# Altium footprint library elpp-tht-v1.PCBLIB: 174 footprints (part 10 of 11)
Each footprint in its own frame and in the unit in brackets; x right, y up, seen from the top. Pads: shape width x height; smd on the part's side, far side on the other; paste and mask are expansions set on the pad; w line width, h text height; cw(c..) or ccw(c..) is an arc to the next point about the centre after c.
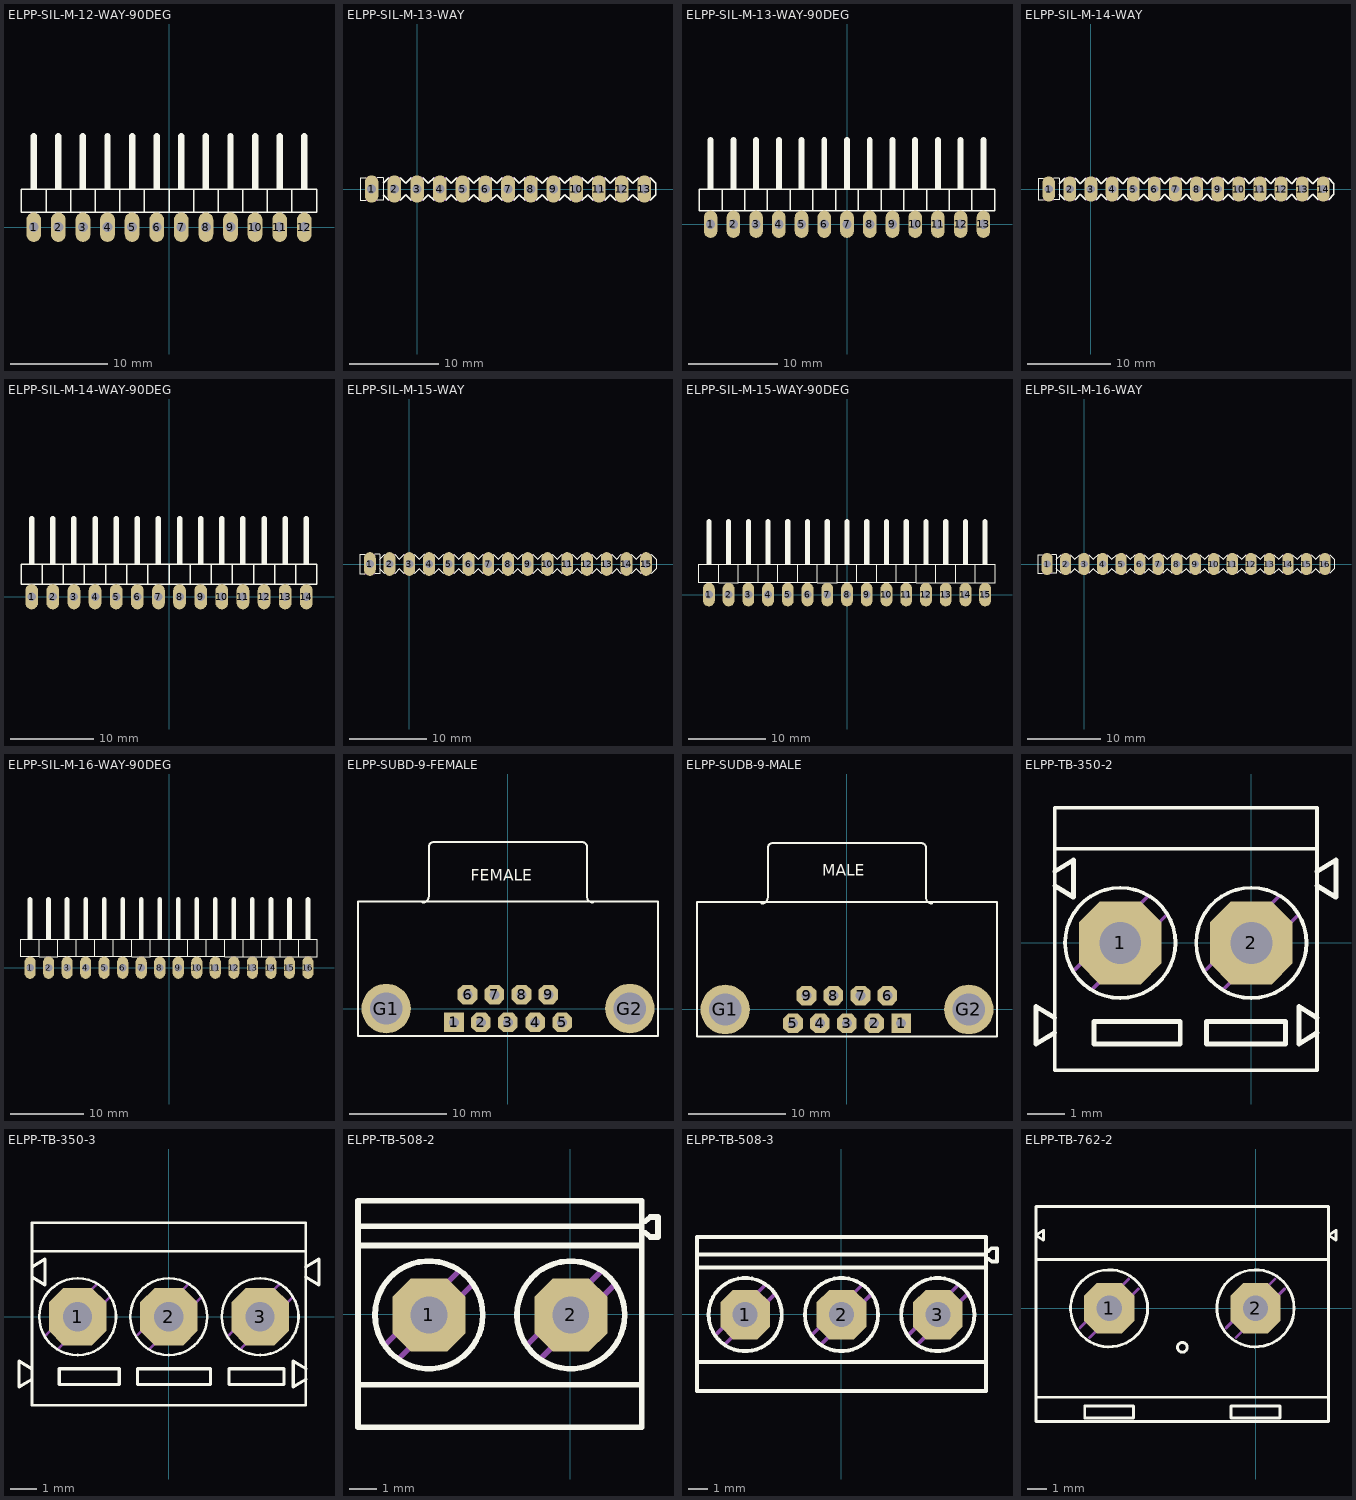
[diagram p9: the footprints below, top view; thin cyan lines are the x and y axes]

## ELPP-SIL-M-12-WAY-90DEG [mil]
pads (12):
  oval 60x120 hole 40: 1(-550,0) 2(-450,0) 3(-350,0) 4(-250,0) 5(-150,0) 6(-50,0) 7(50,0) 8(150,0) 9(250,0) 10(350,0) 11(450,0) 12(550,0)
Top Overlay:
  rectangle: 437,155 463,185
  rectangle: 537,155 563,185
  rectangle: -63,155 -37,185
  rectangle: 37,155 63,185
  rectangle: 137,155 163,185
  rectangle: 237,155 263,185
  rectangle: 337,155 363,185
  rectangle: -563,155 -537,185
  rectangle: -463,155 -437,185
  rectangle: -363,155 -337,185
  rectangle: -263,155 -237,185
  rectangle: -163,155 -137,185
  lines w6: -500,60 -500,155 ; -500,60 -600,60 -600,155 -500,155 ; -500,60 -400,60 ; -500,155 -400,155 ; -400,60 -300,60 ; -400,60 -400,155 ; -400,155 -300,155 ; -300,60 -200,60 ; -300,60 -300,155 ; -300,155 -200,155 ; -200,60 -100,60 ; -200,60 -200,155 ; -200,155 -100,155 ; -100,60 0,60 ; -100,60 -100,155 ; -100,155 0,155 ; 0,60 0,155 ; 0,60 100,60 ; 0,155 100,155 ; 100,60 200,60 ; 100,60 100,155 ; 100,155 200,155 ; 200,60 300,60 ; 200,60 200,155 ; 200,155 300,155 ; 300,60 400,60 ; 300,60 300,155 ; 300,155 400,155 ; 400,60 500,60 ; 400,60 400,155 ; 400,155 500,155 ; 500,60 500,155 ; 500,60 600,60 600,155 500,155
  lines w26: -550,185 -550,370 ; -450,185 -450,370 ; -350,185 -350,370 ; -250,185 -250,370 ; -150,185 -150,370 ; -50,185 -50,370 ; 50,185 50,370 ; 150,185 150,370 ; 250,185 250,370 ; 350,185 350,370 ; 450,185 450,370 ; 550,185 550,370
Mechanical 2:
  text ">NAME" at -610,140 h42.5
Mechanical 4:
  text ">VALUE" at 620,95 h42.5
Mechanical 16:
  rectangle: 537,34 563,60
  rectangle: 437,34 463,60
  rectangle: 337,34 363,60
  rectangle: 537,-13 563,34
  rectangle: 437,-13 463,34
  rectangle: 337,-13 363,34
  rectangle: 237,34 263,60
  rectangle: 137,34 163,60
  rectangle: 237,-13 263,34
  rectangle: 137,-13 163,34
  rectangle: 37,34 63,60
  rectangle: 37,-13 63,34
  rectangle: -63,34 -37,60
  rectangle: -63,-13 -37,34
  rectangle: -163,34 -137,60
  rectangle: -263,34 -237,60
  rectangle: -363,34 -337,60
  rectangle: -163,-13 -137,34
  rectangle: -263,-13 -237,34
  rectangle: -363,-13 -337,34
  rectangle: -463,34 -437,60
  rectangle: -563,34 -537,60
  rectangle: -463,-13 -437,34
  rectangle: -563,-13 -537,34
  text "1" at -525,95 h77.5
  text "2" at -425,95 h77.5
  text "3" at -325,95 h77.5
  text "4" at -225,95 h77.5
  text "5" at -125,95 h77.5
  text "6" at -25,95 h77.5
  text "7" at 75,95 h77.5
  text "8" at 175,95 h77.5
  text "9" at 275,95 h77.5
  text "10" at 375,75 h77.5
  text "11" at 475,75 h77.5
  text "12" at 575,75 h77.5

## ELPP-SIL-M-13-WAY [mil]
pads (13):
  oval 60x120 hole 40: 1(-200,0) 2(-100,0) 3(0,0) 4(100,0) 5(200,0) 6(300,0) 7(400,0) 8(500,0) 9(600,0) 10(700,0) 11(800,0) 12(900,0) 13(1000,0)
Top Overlay:
  lines w5: -225,-50 -250,-50 -250,50 -225,50 ; -175,-50 -150,-50 -150,50 -175,50
  lines w6: -150,-25 -125,-50 ; -150,25 -125,50 ; -75,-50 -50,-25 -25,-50 ; -75,50 -50,25 -25,50 ; 25,-50 50,-25 75,-50 ; 25,50 50,25 75,50 ; 125,-50 150,-25 175,-50 ; 125,50 150,25 175,50 ; 225,-50 250,-25 275,-50 ; 225,50 250,25 275,50 ; 325,-50 350,-25 375,-50 ; 325,50 350,25 375,50 ; 425,-50 450,-25 475,-50 ; 425,50 450,25 475,50 ; 525,-50 550,-25 575,-50 ; 525,50 550,25 575,50 ; 625,-50 650,-25 675,-50 ; 625,50 650,25 675,50 ; 725,-50 750,-25 775,-50 ; 725,50 750,25 775,50 ; 825,-50 850,-25 875,-50 ; 825,50 850,25 875,50 ; 925,-50 950,-25 975,-50 ; 925,50 950,25 975,50 ; 1025,-50 1050,-25 1050,25 1025,50
Mechanical 2:
  text ">NAME" at -250,75 h42.5
Mechanical 4:
  text ">VALUE" at -250,-125 h42.5
Mechanical 16:
  rectangle: -110,-10 -90,10
  rectangle: -210,-10 -190,10
  rectangle: -10,-10 10,10
  rectangle: 190,-10 210,10
  rectangle: 90,-10 110,10
  rectangle: 290,-10 310,10
  rectangle: 390,-10 410,10
  rectangle: 490,-10 510,10
  rectangle: 590,-10 610,10
  rectangle: 690,-10 710,10
  rectangle: 790,-10 810,10
  rectangle: 890,-10 910,10
  rectangle: 990,-10 1010,10
  lines w5: -225,-50 -175,-50 ; -225,50 -175,50
  lines w6: -125,-50 -75,-50 ; -125,50 -75,50 ; -25,-50 25,-50 ; -25,50 25,50 ; 75,-50 125,-50 ; 75,50 125,50 ; 175,-50 225,-50 ; 175,50 225,50 ; 275,-50 325,-50 ; 275,50 325,50 ; 375,-50 425,-50 ; 375,50 425,50 ; 475,-50 525,-50 ; 475,50 525,50 ; 575,-50 625,-50 ; 575,50 625,50 ; 675,-50 725,-50 ; 675,50 725,50 ; 775,-50 825,-50 ; 775,50 825,50 ; 875,-50 925,-50 ; 875,50 925,50 ; 975,-50 1025,-50 ; 975,50 1025,50

## ELPP-SIL-M-13-WAY-90DEG [mil]
pads (13):
  oval 60x120 hole 40: 1(-600,0) 2(-500,0) 3(-400,0) 4(-300,0) 5(-200,0) 6(-100,0) 7(0,0) 8(100,0) 9(200,0) 10(300,0) 11(400,0) 12(500,0) 13(600,0)
Top Overlay:
  rectangle: 387,155 413,185
  rectangle: 487,155 513,185
  rectangle: -113,155 -87,185
  rectangle: -13,155 13,185
  rectangle: 87,155 113,185
  rectangle: 187,155 213,185
  rectangle: 287,155 313,185
  rectangle: -613,155 -587,185
  rectangle: -513,155 -487,185
  rectangle: -413,155 -387,185
  rectangle: -313,155 -287,185
  rectangle: -213,155 -187,185
  rectangle: 587,155 613,185
  lines w6: -550,60 -550,155 ; -550,60 -650,60 -650,155 -550,155 ; -550,60 -450,60 ; -550,155 -450,155 ; -450,60 -350,60 ; -450,60 -450,155 ; -450,155 -350,155 ; -350,60 -250,60 ; -350,60 -350,155 ; -350,155 -250,155 ; -250,60 -150,60 ; -250,60 -250,155 ; -250,155 -150,155 ; -150,60 -50,60 ; -150,60 -150,155 ; -150,155 -50,155 ; -50,60 -50,155 ; -50,60 50,60 ; -50,155 50,155 ; 50,60 150,60 ; 50,60 50,155 ; 50,155 150,155 ; 150,60 250,60 ; 150,60 150,155 ; 150,155 250,155 ; 250,60 350,60 ; 250,60 250,155 ; 250,155 350,155 ; 350,60 450,60 ; 350,60 350,155 ; 350,155 450,155 ; 450,60 450,155 ; 450,60 550,60 ; 450,155 550,155 ; 550,60 550,155 ; 550,60 650,60 650,155 550,155
  lines w26: -600,185 -600,370 ; -500,185 -500,370 ; -400,185 -400,370 ; -300,185 -300,370 ; -200,185 -200,370 ; -100,185 -100,370 ; 0,185 0,370 ; 100,185 100,370 ; 200,185 200,370 ; 300,185 300,370 ; 400,185 400,370 ; 500,185 500,370 ; 600,185 600,370
Mechanical 2:
  text ">NAME" at -660,140 h42.5
Mechanical 4:
  text ">VALUE" at 670,95 h42.5
Mechanical 16:
  rectangle: 487,34 513,60
  rectangle: 387,34 413,60
  rectangle: 287,34 313,60
  rectangle: 487,-13 513,34
  rectangle: 387,-13 413,34
  rectangle: 287,-13 313,34
  rectangle: 187,34 213,60
  rectangle: 87,34 113,60
  rectangle: 187,-13 213,34
  rectangle: 87,-13 113,34
  rectangle: -13,34 13,60
  rectangle: -13,-13 13,34
  rectangle: -113,34 -87,60
  rectangle: -113,-13 -87,34
  rectangle: -213,34 -187,60
  rectangle: -313,34 -287,60
  rectangle: -413,34 -387,60
  rectangle: -213,-13 -187,34
  rectangle: -313,-13 -287,34
  rectangle: -413,-13 -387,34
  rectangle: -513,34 -487,60
  rectangle: -613,34 -587,60
  rectangle: -513,-13 -487,34
  rectangle: -613,-13 -587,34
  rectangle: 587,-13 613,34
  rectangle: 587,34 613,60
  text "1" at -575,95 h77.5
  text "2" at -475,95 h77.5
  text "3" at -375,95 h77.5
  text "4" at -275,95 h77.5
  text "5" at -175,95 h77.5
  text "6" at -75,95 h77.5
  text "7" at 25,95 h77.5
  text "8" at 125,95 h77.5
  text "9" at 225,95 h77.5
  text "10" at 325,75 h77.5
  text "11" at 425,75 h77.5
  text "12" at 525,75 h77.5
  text "13" at 625,75 h77.5

## ELPP-SIL-M-14-WAY [mil]
pads (14):
  oval 60x120 hole 40: 1(-200,0) 2(-100,0) 3(0,0) 4(100,0) 5(200,0) 6(300,0) 7(400,0) 8(500,0) 9(600,0) 10(700,0) 11(800,0) 12(900,0) 13(1000,0) 14(1100,0)
Top Overlay:
  lines w5: -225,-50 -250,-50 -250,50 -225,50 ; -175,-50 -150,-50 -150,50 -175,50
  lines w6: -150,-25 -125,-50 ; -150,25 -125,50 ; -75,-50 -50,-25 -25,-50 ; -75,50 -50,25 -25,50 ; 25,-50 50,-25 75,-50 ; 25,50 50,25 75,50 ; 125,-50 150,-25 175,-50 ; 125,50 150,25 175,50 ; 225,-50 250,-25 275,-50 ; 225,50 250,25 275,50 ; 325,-50 350,-25 375,-50 ; 325,50 350,25 375,50 ; 425,-50 450,-25 475,-50 ; 425,50 450,25 475,50 ; 525,-50 550,-25 575,-50 ; 525,50 550,25 575,50 ; 625,-50 650,-25 675,-50 ; 625,50 650,25 675,50 ; 725,-50 750,-25 775,-50 ; 725,50 750,25 775,50 ; 825,-50 850,-25 875,-50 ; 825,50 850,25 875,50 ; 925,-50 950,-25 975,-50 ; 925,50 950,25 975,50 ; 1025,-50 1050,-25 1075,-50 ; 1025,50 1050,25 1075,50 ; 1125,-50 1150,-25 1150,25 1125,50
Mechanical 2:
  text ">NAME" at -250,75 h42.5
Mechanical 4:
  text ">VALUE" at -250,-125 h42.5
Mechanical 16:
  rectangle: -110,-10 -90,10
  rectangle: -210,-10 -190,10
  rectangle: -10,-10 10,10
  rectangle: 190,-10 210,10
  rectangle: 90,-10 110,10
  rectangle: 290,-10 310,10
  rectangle: 390,-10 410,10
  rectangle: 490,-10 510,10
  rectangle: 590,-10 610,10
  rectangle: 690,-10 710,10
  rectangle: 790,-10 810,10
  rectangle: 890,-10 910,10
  rectangle: 990,-10 1010,10
  rectangle: 1090,-10 1110,10
  lines w5: -225,-50 -175,-50 ; -225,50 -175,50
  lines w6: -125,-50 -75,-50 ; -125,50 -75,50 ; -25,-50 25,-50 ; -25,50 25,50 ; 75,-50 125,-50 ; 75,50 125,50 ; 175,-50 225,-50 ; 175,50 225,50 ; 275,-50 325,-50 ; 275,50 325,50 ; 375,-50 425,-50 ; 375,50 425,50 ; 475,-50 525,-50 ; 475,50 525,50 ; 575,-50 625,-50 ; 575,50 625,50 ; 675,-50 725,-50 ; 675,50 725,50 ; 775,-50 825,-50 ; 775,50 825,50 ; 875,-50 925,-50 ; 875,50 925,50 ; 975,-50 1025,-50 ; 975,50 1025,50 ; 1075,-50 1125,-50 ; 1075,50 1125,50

## ELPP-SIL-M-14-WAY-90DEG [mil]
pads (14):
  oval 60x120 hole 40: 1(-650,0) 2(-550,0) 3(-450,0) 4(-350,0) 5(-250,0) 6(-150,0) 7(-50,0) 8(50,0) 9(150,0) 10(250,0) 11(350,0) 12(450,0) 13(550,0) 14(650,0)
Top Overlay:
  rectangle: 337,155 363,185
  rectangle: 437,155 463,185
  rectangle: -163,155 -137,185
  rectangle: -63,155 -37,185
  rectangle: 37,155 63,185
  rectangle: 137,155 163,185
  rectangle: 237,155 263,185
  rectangle: -663,155 -637,185
  rectangle: -563,155 -537,185
  rectangle: -463,155 -437,185
  rectangle: -363,155 -337,185
  rectangle: -263,155 -237,185
  rectangle: 537,155 563,185
  rectangle: 637,155 663,185
  lines w6: -600,60 -600,155 ; -600,60 -700,60 -700,155 -600,155 ; -600,60 -500,60 ; -600,155 -500,155 ; -500,60 -400,60 ; -500,60 -500,155 ; -500,155 -400,155 ; -400,60 -300,60 ; -400,60 -400,155 ; -400,155 -300,155 ; -300,60 -200,60 ; -300,60 -300,155 ; -300,155 -200,155 ; -200,60 -100,60 ; -200,60 -200,155 ; -200,155 -100,155 ; -100,60 -100,155 ; -100,60 0,60 ; -100,155 0,155 ; 0,60 100,60 ; 0,60 0,155 ; 0,155 100,155 ; 100,60 200,60 ; 100,60 100,155 ; 100,155 200,155 ; 200,60 300,60 ; 200,60 200,155 ; 200,155 300,155 ; 300,60 400,60 ; 300,60 300,155 ; 300,155 400,155 ; 400,60 400,155 ; 400,60 500,60 ; 400,155 500,155 ; 500,60 500,155 ; 500,60 600,60 ; 500,155 600,155 ; 600,60 600,155 ; 600,60 700,60 700,155 600,155
  lines w26: -650,185 -650,370 ; -550,185 -550,370 ; -450,185 -450,370 ; -350,185 -350,370 ; -250,185 -250,370 ; -150,185 -150,370 ; -50,185 -50,370 ; 50,185 50,370 ; 150,185 150,370 ; 250,185 250,370 ; 350,185 350,370 ; 450,185 450,370 ; 550,185 550,370 ; 650,185 650,370
Mechanical 2:
  text ">NAME" at -710,140 h42.5
Mechanical 4:
  text ">VALUE" at 720,95 h42.5
Mechanical 16:
  rectangle: 437,34 463,60
  rectangle: 337,34 363,60
  rectangle: 237,34 263,60
  rectangle: 437,-13 463,34
  rectangle: 337,-13 363,34
  rectangle: 237,-13 263,34
  rectangle: 137,34 163,60
  rectangle: 37,34 63,60
  rectangle: 137,-13 163,34
  rectangle: 37,-13 63,34
  rectangle: -63,34 -37,60
  rectangle: -63,-13 -37,34
  rectangle: -163,34 -137,60
  rectangle: -163,-13 -137,34
  rectangle: -263,34 -237,60
  rectangle: -363,34 -337,60
  rectangle: -463,34 -437,60
  rectangle: -263,-13 -237,34
  rectangle: -363,-13 -337,34
  rectangle: -463,-13 -437,34
  rectangle: -563,34 -537,60
  rectangle: -663,34 -637,60
  rectangle: -563,-13 -537,34
  rectangle: -663,-13 -637,34
  rectangle: 537,-13 563,34
  rectangle: 537,34 563,60
  rectangle: 637,-13 663,34
  rectangle: 637,34 663,60
  text "1" at -625,95 h77.5
  text "2" at -525,95 h77.5
  text "3" at -425,95 h77.5
  text "4" at -325,95 h77.5
  text "5" at -225,95 h77.5
  text "6" at -125,95 h77.5
  text "7" at -25,95 h77.5
  text "8" at 75,95 h77.5
  text "9" at 175,95 h77.5
  text "10" at 275,75 h77.5
  text "11" at 375,75 h77.5
  text "12" at 475,75 h77.5
  text "13" at 575,75 h77.5
  text "14" at 675,75 h77.5

## ELPP-SIL-M-15-WAY [mil]
pads (15):
  oval 60x120 hole 40: 1(-200,0) 2(-100,0) 3(0,0) 4(100,0) 5(200,0) 6(300,0) 7(400,0) 8(500,0) 9(600,0) 10(700,0) 11(800,0) 12(900,0) 13(1000,0) 14(1100,0) 15(1200,0)
Top Overlay:
  lines w5: -225,-50 -250,-50 -250,50 -225,50 ; -175,-50 -150,-50 -150,50 -175,50
  lines w6: -150,-25 -125,-50 ; -150,25 -125,50 ; -75,-50 -50,-25 -25,-50 ; -75,50 -50,25 -25,50 ; 25,-50 50,-25 75,-50 ; 25,50 50,25 75,50 ; 125,-50 150,-25 175,-50 ; 125,50 150,25 175,50 ; 225,-50 250,-25 275,-50 ; 225,50 250,25 275,50 ; 325,-50 350,-25 375,-50 ; 325,50 350,25 375,50 ; 425,-50 450,-25 475,-50 ; 425,50 450,25 475,50 ; 525,-50 550,-25 575,-50 ; 525,50 550,25 575,50 ; 625,-50 650,-25 675,-50 ; 625,50 650,25 675,50 ; 725,-50 750,-25 775,-50 ; 725,50 750,25 775,50 ; 825,-50 850,-25 875,-50 ; 825,50 850,25 875,50 ; 925,-50 950,-25 975,-50 ; 925,50 950,25 975,50 ; 1025,-50 1050,-25 1075,-50 ; 1025,50 1050,25 1075,50 ; 1125,-50 1150,-25 1175,-50 ; 1125,50 1150,25 1175,50 ; 1225,-50 1250,-25 1250,25 1225,50
Mechanical 2:
  text ">NAME" at -250,75 h42.5
Mechanical 4:
  text ">VALUE" at -250,-125 h42.5
Mechanical 16:
  rectangle: -110,-10 -90,10
  rectangle: -210,-10 -190,10
  rectangle: -10,-10 10,10
  rectangle: 190,-10 210,10
  rectangle: 90,-10 110,10
  rectangle: 290,-10 310,10
  rectangle: 390,-10 410,10
  rectangle: 490,-10 510,10
  rectangle: 590,-10 610,10
  rectangle: 690,-10 710,10
  rectangle: 790,-10 810,10
  rectangle: 890,-10 910,10
  rectangle: 990,-10 1010,10
  rectangle: 1090,-10 1110,10
  rectangle: 1190,-10 1210,10
  lines w5: -225,-50 -175,-50 ; -225,50 -175,50
  lines w6: -125,-50 -75,-50 ; -125,50 -75,50 ; -25,-50 25,-50 ; -25,50 25,50 ; 75,-50 125,-50 ; 75,50 125,50 ; 175,-50 225,-50 ; 175,50 225,50 ; 275,-50 325,-50 ; 275,50 325,50 ; 375,-50 425,-50 ; 375,50 425,50 ; 475,-50 525,-50 ; 475,50 525,50 ; 575,-50 625,-50 ; 575,50 625,50 ; 675,-50 725,-50 ; 675,50 725,50 ; 775,-50 825,-50 ; 775,50 825,50 ; 875,-50 925,-50 ; 875,50 925,50 ; 975,-50 1025,-50 ; 975,50 1025,50 ; 1075,-50 1125,-50 ; 1075,50 1125,50 ; 1175,-50 1225,-50 ; 1175,50 1225,50

## ELPP-SIL-M-15-WAY-90DEG [mil]
pads (15):
  oval 60x120 hole 40: 1(-700,0) 2(-600,0) 3(-500,0) 4(-400,0) 5(-300,0) 6(-200,0) 7(-100,0) 8(0,0) 9(100,0) 10(200,0) 11(300,0) 12(400,0) 13(500,0) 14(600,0) 15(700,0)
Top Overlay:
  rectangle: 287,155 313,185
  rectangle: 387,155 413,185
  rectangle: -213,155 -187,185
  rectangle: -113,155 -87,185
  rectangle: -13,155 13,185
  rectangle: 87,155 113,185
  rectangle: 187,155 213,185
  rectangle: -713,155 -687,185
  rectangle: -613,155 -587,185
  rectangle: -513,155 -487,185
  rectangle: -413,155 -387,185
  rectangle: -313,155 -287,185
  rectangle: 487,155 513,185
  rectangle: 587,155 613,185
  rectangle: 687,155 713,185
  lines w6: -650,60 -650,155 ; -650,60 -750,60 -750,155 -650,155 ; -650,60 -550,60 ; -650,155 -550,155 ; -550,60 -450,60 ; -550,60 -550,155 ; -550,155 -450,155 ; -450,60 -350,60 ; -450,60 -450,155 ; -450,155 -350,155 ; -350,60 -250,60 ; -350,60 -350,155 ; -350,155 -250,155 ; -250,60 -150,60 ; -250,60 -250,155 ; -250,155 -150,155 ; -150,60 -150,155 ; -150,60 -50,60 ; -150,155 -50,155 ; -50,60 50,60 ; -50,60 -50,155 ; -50,155 50,155 ; 50,60 150,60 ; 50,60 50,155 ; 50,155 150,155 ; 150,60 250,60 ; 150,60 150,155 ; 150,155 250,155 ; 250,60 350,60 ; 250,60 250,155 ; 250,155 350,155 ; 350,60 350,155 ; 350,60 450,60 ; 350,155 450,155 ; 450,60 450,155 ; 450,60 550,60 ; 450,155 550,155 ; 550,60 550,155 ; 550,60 650,60 ; 550,155 650,155 ; 650,60 650,155 ; 650,60 750,60 750,155 650,155
  lines w26: -700,185 -700,370 ; -600,185 -600,370 ; -500,185 -500,370 ; -400,185 -400,370 ; -300,185 -300,370 ; -200,185 -200,370 ; -100,185 -100,370 ; 0,185 0,370 ; 100,185 100,370 ; 200,185 200,370 ; 300,185 300,370 ; 400,185 400,370 ; 500,185 500,370 ; 600,185 600,370 ; 700,185 700,370
Mechanical 2:
  text ">NAME" at -760,140 h42.5
Mechanical 4:
  text ">VALUE" at 770,95 h42.5
Mechanical 16:
  rectangle: 387,34 413,60
  rectangle: 287,34 313,60
  rectangle: 187,34 213,60
  rectangle: 387,-13 413,34
  rectangle: 287,-13 313,34
  rectangle: 187,-13 213,34
  rectangle: 87,34 113,60
  rectangle: -13,34 13,60
  rectangle: 87,-13 113,34
  rectangle: -13,-13 13,34
  rectangle: -113,34 -87,60
  rectangle: -113,-13 -87,34
  rectangle: -213,34 -187,60
  rectangle: -213,-13 -187,34
  rectangle: -313,34 -287,60
  rectangle: -413,34 -387,60
  rectangle: -513,34 -487,60
  rectangle: -313,-13 -287,34
  rectangle: -413,-13 -387,34
  rectangle: -513,-13 -487,34
  rectangle: -613,34 -587,60
  rectangle: -713,34 -687,60
  rectangle: -613,-13 -587,34
  rectangle: -713,-13 -687,34
  rectangle: 487,-13 513,34
  rectangle: 487,34 513,60
  rectangle: 587,-13 613,34
  rectangle: 587,34 613,60
  rectangle: 687,-13 713,34
  rectangle: 687,34 713,60
  text "1" at -675,95 h77.5
  text "2" at -575,95 h77.5
  text "3" at -475,95 h77.5
  text "4" at -375,95 h77.5
  text "5" at -275,95 h77.5
  text "6" at -175,95 h77.5
  text "7" at -75,95 h77.5
  text "8" at 25,95 h77.5
  text "9" at 125,95 h77.5
  text "10" at 225,75 h77.5
  text "11" at 325,75 h77.5
  text "12" at 425,75 h77.5
  text "13" at 525,75 h77.5
  text "14" at 625,75 h77.5
  text "15" at 725,75 h77.5

## ELPP-SIL-M-16-WAY [mil]
pads (16):
  oval 60x120 hole 40: 1(-200,0) 2(-100,0) 3(0,0) 4(100,0) 5(200,0) 6(300,0) 7(400,0) 8(500,0) 9(600,0) 10(700,0) 11(800,0) 12(900,0) 13(1000,0) 14(1100,0) 15(1200,0) 16(1300,0)
Top Overlay:
  lines w5: -225,-50 -250,-50 -250,50 -225,50 ; -175,-50 -150,-50 -150,50 -175,50
  lines w6: -150,-25 -125,-50 ; -150,25 -125,50 ; -75,-50 -50,-25 -25,-50 ; -75,50 -50,25 -25,50 ; 25,-50 50,-25 75,-50 ; 25,50 50,25 75,50 ; 125,-50 150,-25 175,-50 ; 125,50 150,25 175,50 ; 225,-50 250,-25 275,-50 ; 225,50 250,25 275,50 ; 325,-50 350,-25 375,-50 ; 325,50 350,25 375,50 ; 425,-50 450,-25 475,-50 ; 425,50 450,25 475,50 ; 525,-50 550,-25 575,-50 ; 525,50 550,25 575,50 ; 625,-50 650,-25 675,-50 ; 625,50 650,25 675,50 ; 725,-50 750,-25 775,-50 ; 725,50 750,25 775,50 ; 825,-50 850,-25 875,-50 ; 825,50 850,25 875,50 ; 925,-50 950,-25 975,-50 ; 925,50 950,25 975,50 ; 1025,-50 1050,-25 1075,-50 ; 1025,50 1050,25 1075,50 ; 1125,-50 1150,-25 1175,-50 ; 1125,50 1150,25 1175,50 ; 1225,-50 1250,-25 1275,-50 ; 1225,50 1250,25 1275,50 ; 1325,-50 1350,-25 1350,25 1325,50
Mechanical 2:
  text ">NAME" at -250,75 h42.5
Mechanical 4:
  text ">VALUE" at -250,-125 h42.5
Mechanical 16:
  rectangle: -110,-10 -90,10
  rectangle: -210,-10 -190,10
  rectangle: -10,-10 10,10
  rectangle: 190,-10 210,10
  rectangle: 90,-10 110,10
  rectangle: 290,-10 310,10
  rectangle: 390,-10 410,10
  rectangle: 490,-10 510,10
  rectangle: 590,-10 610,10
  rectangle: 690,-10 710,10
  rectangle: 790,-10 810,10
  rectangle: 890,-10 910,10
  rectangle: 990,-10 1010,10
  rectangle: 1090,-10 1110,10
  rectangle: 1190,-10 1210,10
  rectangle: 1290,-10 1310,10
  lines w5: -225,-50 -175,-50 ; -225,50 -175,50
  lines w6: -125,-50 -75,-50 ; -125,50 -75,50 ; -25,-50 25,-50 ; -25,50 25,50 ; 75,-50 125,-50 ; 75,50 125,50 ; 175,-50 225,-50 ; 175,50 225,50 ; 275,-50 325,-50 ; 275,50 325,50 ; 375,-50 425,-50 ; 375,50 425,50 ; 475,-50 525,-50 ; 475,50 525,50 ; 575,-50 625,-50 ; 575,50 625,50 ; 675,-50 725,-50 ; 675,50 725,50 ; 775,-50 825,-50 ; 775,50 825,50 ; 875,-50 925,-50 ; 875,50 925,50 ; 975,-50 1025,-50 ; 975,50 1025,50 ; 1075,-50 1125,-50 ; 1075,50 1125,50 ; 1175,-50 1225,-50 ; 1175,50 1225,50 ; 1275,-50 1325,-50 ; 1275,50 1325,50

## ELPP-SIL-M-16-WAY-90DEG [mil]
pads (16):
  oval 60x120 hole 40: 1(-750,0) 2(-650,0) 3(-550,0) 4(-450,0) 5(-350,0) 6(-250,0) 7(-150,0) 8(-50,0) 9(50,0) 10(150,0) 11(250,0) 12(350,0) 13(450,0) 14(550,0) 15(650,0) 16(750,0)
Top Overlay:
  rectangle: 237,155 263,185
  rectangle: 337,155 363,185
  rectangle: -263,155 -237,185
  rectangle: -163,155 -137,185
  rectangle: -63,155 -37,185
  rectangle: 37,155 63,185
  rectangle: 137,155 163,185
  rectangle: -763,155 -737,185
  rectangle: -663,155 -637,185
  rectangle: -563,155 -537,185
  rectangle: -463,155 -437,185
  rectangle: -363,155 -337,185
  rectangle: 437,155 463,185
  rectangle: 537,155 563,185
  rectangle: 637,155 663,185
  rectangle: 737,155 763,185
  lines w6: -700,60 -700,155 ; -700,60 -800,60 -800,155 -700,155 ; -700,60 -600,60 ; -700,155 -600,155 ; -600,60 -500,60 ; -600,60 -600,155 ; -600,155 -500,155 ; -500,60 -400,60 ; -500,60 -500,155 ; -500,155 -400,155 ; -400,60 -300,60 ; -400,60 -400,155 ; -400,155 -300,155 ; -300,60 -200,60 ; -300,60 -300,155 ; -300,155 -200,155 ; -200,60 -200,155 ; -200,60 -100,60 ; -200,155 -100,155 ; -100,60 0,60 ; -100,60 -100,155 ; -100,155 0,155 ; 0,60 100,60 ; 0,60 0,155 ; 0,155 100,155 ; 100,60 200,60 ; 100,60 100,155 ; 100,155 200,155 ; 200,60 300,60 ; 200,60 200,155 ; 200,155 300,155 ; 300,60 300,155 ; 300,60 400,60 ; 300,155 400,155 ; 400,60 400,155 ; 400,60 500,60 ; 400,155 500,155 ; 500,60 500,155 ; 500,60 600,60 ; 500,155 600,155 ; 600,60 600,155 ; 600,60 700,60 ; 600,155 700,155 ; 700,60 700,155 ; 700,60 800,60 800,155 700,155
  lines w26: -750,185 -750,370 ; -650,185 -650,370 ; -550,185 -550,370 ; -450,185 -450,370 ; -350,185 -350,370 ; -250,185 -250,370 ; -150,185 -150,370 ; -50,185 -50,370 ; 50,185 50,370 ; 150,185 150,370 ; 250,185 250,370 ; 350,185 350,370 ; 450,185 450,370 ; 550,185 550,370 ; 650,185 650,370 ; 750,185 750,370
Mechanical 2:
  text ">NAME" at -810,140 h42.5
Mechanical 4:
  text ">VALUE" at 820,95 h42.5
Mechanical 16:
  rectangle: 337,34 363,60
  rectangle: 237,34 263,60
  rectangle: 137,34 163,60
  rectangle: 337,-13 363,34
  rectangle: 237,-13 263,34
  rectangle: 137,-13 163,34
  rectangle: 37,34 63,60
  rectangle: -63,34 -37,60
  rectangle: 37,-13 63,34
  rectangle: -63,-13 -37,34
  rectangle: -163,34 -137,60
  rectangle: -163,-13 -137,34
  rectangle: -263,34 -237,60
  rectangle: -263,-13 -237,34
  rectangle: -363,34 -337,60
  rectangle: -463,34 -437,60
  rectangle: -563,34 -537,60
  rectangle: -363,-13 -337,34
  rectangle: -463,-13 -437,34
  rectangle: -563,-13 -537,34
  rectangle: -663,34 -637,60
  rectangle: -763,34 -737,60
  rectangle: -663,-13 -637,34
  rectangle: -763,-13 -737,34
  rectangle: 437,-13 463,34
  rectangle: 437,34 463,60
  rectangle: 537,-13 563,34
  rectangle: 537,34 563,60
  rectangle: 637,-13 663,34
  rectangle: 637,34 663,60
  rectangle: 737,-13 763,34
  rectangle: 737,34 763,60
  text "1" at -725,95 h77.5
  text "2" at -625,95 h77.5
  text "3" at -525,95 h77.5
  text "4" at -425,95 h77.5
  text "5" at -325,95 h77.5
  text "6" at -225,95 h77.5
  text "7" at -125,95 h77.5
  text "8" at -25,95 h77.5
  text "9" at 75,95 h77.5
  text "10" at 175,75 h77.5
  text "11" at 275,75 h77.5
  text "12" at 375,75 h77.5
  text "13" at 475,75 h77.5
  text "14" at 575,75 h77.5
  text "15" at 675,75 h77.5
  text "16" at 775,75 h77.5

## ELPP-SUBD-9-FEMALE [mil]
pads (11):
  rect 79x79 hole 40: 1(-218.11,-55.91)
  oct 79x79 hole 40: 2(-109.06,-55.91) 3(0,-55.91) 4(110,-55.91) 5(219,-55.91) 6(-163.39,56) 7(-54.33,56) 8(55,56) 9(164,56)
  round 200 hole 130: G1(-492.13,0) G2(493,0)
Top Overlay:
  lines w8: -606.3,100 -606.3,-110.24 607,-110.24 607,100 607,434 -606.3,434 -606.3,101 ; -345,428 ccw(c-345,453) -320,453 -320,653 cw(c-300,653) -300,673 300,673 cw(c300,653) 320,653 320,453 ccw(c345,453) 345,428
  text "FEMALE" at -150,500 h77.5
Mechanical 2:
  text ">NAME" at -581.3,-196.85 h42.5
Mechanical 4:
  text ">VALUE" at -127.17,210 h42.5

## ELPP-SUDB-9-MALE [mil]
pads (11):
  rect 79x79 hole 40: 1(219,-55.91)
  oct 79x79 hole 40: 2(110,-55.91) 3(0,-55.91) 4(-109.06,-55.91) 5(-218.11,-55.91) 6(164,56) 7(55,56) 8(-54.33,56) 9(-163.39,56)
  round 200 hole 130: G1(-492.13,0) G2(493,0)
Top Overlay:
  lines w8: -606.3,100 -606.3,-110.24 607,-110.24 607,100 607,434 -606.3,434 -606.3,101 ; -345,428 ccw(c-345,453) -320,453 -320,653 cw(c-300,653) -300,673 300,673 cw(c300,653) 320,653 320,453 ccw(c345,453) 345,428
  text "MALE" at -100,525 h77.5
Mechanical 2:
  text ">NAME" at -581.3,-196.85 h42.5
Mechanical 4:
  text ">VALUE" at -152.17,185 h42.5

## ELPP-TB-350-2 [mil]
pads (2):
  oct 87x87 hole 44: 1(-137.8,0) 2(0,0)
Top Overlay:
  circle w4: c-137.8,0 r58
  circle w4: c0,0 r58
  lines w4: -206.69,99 69,99 ; -206.69,-133.86 69,-133.86 69,142 -206.69,142 -206.69,-133.86
  lines w5: -206.69,-94.49 -226.38,-106.3 -226.38,-78.74 -226.38,-66.93 -206.69,-78.74 ; -206.69,60 -187.01,48 -187.01,75 -187.01,87 -206.69,75 ; 69,-94.49 50,-106.3 50,-78.74 50,-66.93 69,-78.74 ; 69,60 89,48 89,75 89,87 69,75 ; -165.35,-106.3 -165.35,-82.68 -74.8,-82.68 -74.8,-106.3 -165.35,-106.3 ; -47.24,-106.3 -47.24,-82.68 36,-82.68 36,-106.3 -47.24,-106.3
Mechanical 2:
  text ">NAME" at -206.99,-194.69 h42.5
Mechanical 4:
  text ">VALUE" at -208.76,155 h42.5
Mechanical 16:
  lines w4: -185.28,-27.99 -109.8,48 ; -165.79,-47.48 -90.55,28 ; -47.48,-27.99 28,48 ; -27.99,-47.48 48,28

## ELPP-TB-350-3 [mil]
pads (3):
  oct 87x87 hole 44: 1(-137.8,0) 2(0,0) 3(138,0)
Top Overlay:
  circle w4: c-137.8,0 r58
  circle w4: c0,0 r58
  circle w4: c138,0 r58
  lines w4: -206.69,99 207,99 ; -206.69,-133.86 207,-133.86 207,142 -206.69,142 -206.69,-133.86
  lines w5: -206.69,-94.49 -226.38,-106.3 -226.38,-78.74 -226.38,-66.93 -206.69,-78.74 ; -206.69,60 -187.01,48 -187.01,75 -187.01,87 -206.69,75 ; 207,-94.49 188,-106.3 188,-78.74 188,-66.93 207,-78.74 ; 207,60 227,48 227,75 227,87 207,75 ; -165.35,-102.36 -165.35,-78.74 -74.8,-78.74 -74.8,-102.36 -165.35,-102.36 ; -47.24,-102.36 -47.24,-78.74 63,-78.74 63,-102.36 -47.24,-102.36 ; 91,-102.36 91,-78.74 174,-78.74 174,-102.36 91,-102.36
Mechanical 2:
  text ">NAME" at -206.99,-194.69 h42.5
Mechanical 4:
  text ">VALUE" at -208.76,155 h42.5
Mechanical 16:
  lines w4: -185.28,-27.99 -109.8,48 ; -165.79,-47.48 -90.55,28 ; -47.48,-27.99 28,48 ; -27.99,-47.48 48,28 ; 91,-27.99 166,48 ; 110,-47.48 186,28

## ELPP-TB-508-2 [mil]
pads (2):
  oct 103x103 hole 52: 1(-199.17,-0.98) 2(1,-0.98)
Top Overlay:
  circle w8: c1,-0.98 r76
  circle w8: c-199.17,-0.98 r76
  lines w8: -299.17,-99.38 101,-99.38 ; -299.17,-99.38 -299.17,-80.37 -299.17,77 -299.17,97 ; -299.17,-99.38 -299.17,-159.45 101,-159.45 101,-99.38 ; -299.17,97 101,97 ; -299.17,97 -299.17,124 ; -299.17,124 101,124 ; -299.17,124 -299.17,148 -299.17,160 101,160 101,148 101,131 ; 101,-99.38 101,-80.37 101,77 101,97 ; 101,97 101,115 ; 101,115 106,115 113,109 124,109 124,137 113,137 106,131 101,131 ; 101,115 101,124 ; 101,124 101,131
Mechanical 2:
  text ">NAME" at -287.05,-225 h42.5
Mechanical 4:
  text ">VALUE" at -300,175 h42.5
Mechanical 16:
  lines w8: -260.9,-43.23 -223.97,-6.3 ; -241.41,-62.72 -203.85,-25.16 ; -156.93,61 -192.87,25 ; -137.44,42 -174.01,5 ; -60.9,-43.23 -23.97,-6.3 ; -41.41,-62.72 -3.85,-25.16 ; 44,61 8,25 ; 63,42 26,5 ; -223.97,-6.3 -199.17,19 -192.87,25 ; -223.97,-6.3 ccw(c-199.17,0) -203.85,-25.16 ; -203.85,-25.16 -199.17,-20.47 -174.01,5 ; -192.87,25 cw(c-199.08,0.26) -174.01,5 ; -23.97,-6.3 1,19 8,25 ; -23.97,-6.3 ccw(c0.83,0) -3.85,-25.16 ; -3.85,-25.16 1,-20.47 26,5 ; 8,25 cw(c1.36,0.93) 26,5

## ELPP-TB-508-3 [mil]
pads (3):
  oct 103x103 hole 52: 1(-199.17,-0.98) 2(1,-0.98) 3(201,-0.98)
Top Overlay:
  circle w8: c201,-0.98 r76
  circle w8: c1,-0.98 r76
  circle w8: c-199.17,-0.98 r76
  lines w8: -299.17,-99.38 301,-99.38 ; -299.17,-99.38 -299.17,-80.37 -299.17,77 -299.17,97 ; -299.17,-99.38 -299.17,-159.45 301,-159.45 301,-99.38 ; -299.17,97 301,97 ; -299.17,97 -299.17,124 ; -299.17,124 301,124 ; -299.17,124 -299.17,148 -299.17,160 301,160 301,148 301,131 ; 301,-99.38 301,-80.37 301,77 301,97 ; 301,97 301,115 ; 301,115 306,115 313,109 324,109 324,137 313,137 306,131 301,131 ; 301,115 301,124 ; 301,124 301,131
Mechanical 2:
  text ">NAME" at -287.05,-225 h42.5
Mechanical 4:
  text ">VALUE" at -300,175 h42.5
Mechanical 16:
  lines w8: -260.9,-43.23 -223.97,-6.3 ; -241.41,-62.72 -203.85,-25.16 ; -156.93,61 -192.87,25 ; -137.44,42 -174.01,5 ; -60.9,-43.23 -23.97,-6.3 ; -41.41,-62.72 -3.85,-25.16 ; 44,61 8,25 ; 63,42 26,5 ; 140,-43.23 177,-6.3 ; 159,-62.72 197,-25.16 ; 244,61 208,25 ; 263,42 226,5 ; -223.97,-6.3 -199.17,19 -192.87,25 ; -223.97,-6.3 ccw(c-199.17,0) -203.85,-25.16 ; -203.85,-25.16 -199.17,-20.47 -174.01,5 ; -192.87,25 cw(c-199.08,0.26) -174.01,5 ; -23.97,-6.3 1,19 8,25 ; -23.97,-6.3 ccw(c0.83,0) -3.85,-25.16 ; -3.85,-25.16 1,-20.47 26,5 ; 8,25 cw(c1.36,0.93) 26,5 ; 177,-6.3 201,19 208,25 ; 177,-6.3 ccw(c201.74,-0.09) 197,-25.16 ; 197,-25.16 201,-20.47 226,5 ; 208,25 cw(c201.36,0.93) 226,5

## ELPP-TB-762-2 [mil]
pads (2):
  oct 103x103 hole 52: 1(-300,0) 2(0,0)
Top Overlay:
  circle w6: c-300,0 r79
  circle w6: c0,0 r79
  circle w6: c-150,-80 r10
  lines w6: -450,-182.28 -450,-232.28 150,-232.28 150,-182.28 ; -450,-182.28 -450,100 ; -450,-182.28 150,-182.28 ; -450,100 150,100 ; -450,100 -450,150 ; -450,150 -450,209 150,209 150,150 ; -450,150 -435,160 -435,140 -450,150 ; 150,-182.28 150,100 ; 150,100 150,150 ; 150,150 165,160 165,140 150,150 ; -350,-225 -350,-200 -250,-200 -250,-225 -350,-225 ; -50,-225 -50,-200 50,-200 50,-225 -50,-225
Mechanical 2:
  text ">NAME" at -450,250 h42.5
Mechanical 4:
  text ">VALUE" at -450,-300 h42.5
Mechanical 16:
  lines w6: -360,-40 -260,60 ; -340,-60 -240,40 ; -60,-40 40,60 ; -40,-60 60,40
